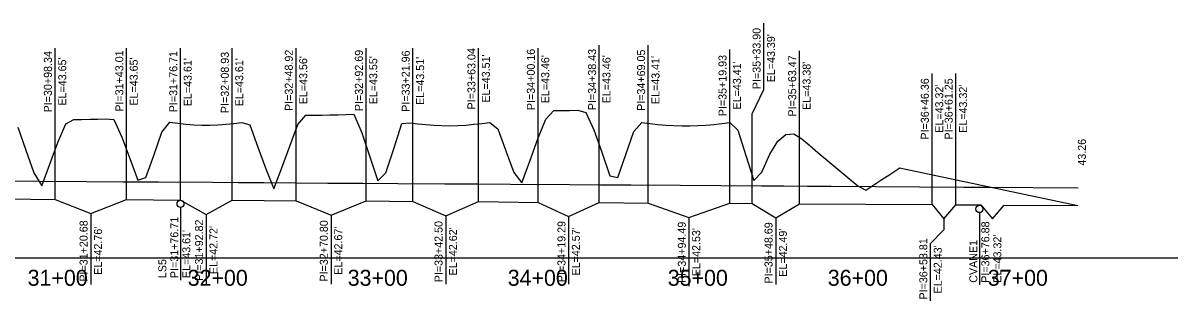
# Model space of a CAD drawing. Extents: x 2394206 to 2397081, y 556531 to 561531.
# Drawn here: x 2396359 to 2397081, y 559004 to 559178 of the extents above; entities that cross this region are included whole.
import ezdxf

# ---------------------------------------------------------------- set-up
doc = ezdxf.new("R2010")
doc.units = 0
for name, color, linetype in [('Default', 7, 'Continuous'), ('Existing ground', 7, 'Continuous'), ('Profile grid', 7, 'Continuous'), ('Proposed bankfull', 7, 'Continuous'), ('Proposed structure lables', 7, 'Continuous'), ('Station lables', 7, 'Continuous')]:
    doc.layers.add(name, color=color, linetype=linetype)

msp = doc.modelspace()

# ---------------------------------------------------------------- linework, layer by layer
at = {"layer": 'Default'}
for p, q in [((2396822.06, 559136.3), (2396822.06, 559177.88)), ((2396379.18, 559067.7), (2396379.18, 559162.16)), ((2396423.85, 559067.66), (2396423.85, 559162.16)), ((2396457.55, 559067.27), (2396457.55, 559162.16)), ((2396489.77, 559067.24), (2396489.77, 559162.16)), ((2396529.76, 559066.76), (2396529.76, 559162.16)), ((2396573.53, 559066.71), (2396573.53, 559162.16)), ((2396602.8, 559066.31), (2396602.8, 559162.16)), ((2396643.88, 559066.27), (2396643.88, 559162.16)), ((2396681, 559065.83), (2396681, 559162.16)), ((2396719.27, 559065.79), (2396719.27, 559164.02)), ((2396749.89, 559065.33), (2396749.89, 559164.02)), ((2396800.77, 559065.28), (2396800.77, 559161.41)), ((2396844.31, 559065.01), (2396844.31, 559160.5)), ((2396927.2, 559064.41), (2396927.2, 559146.32)), ((2396942.09, 559064.39), (2396942.09, 559146.32)), ((2396814.74, 559121.08), (2396822.06, 559136.3)), ((2396814.74, 559065.04), (2396814.74, 559121.08)), ((2396401.52, 559058.8), (2396401.52, 559014.54)), ((2396473.66, 559058.34), (2396473.66, 559014.74)), ((2396551.64, 559057.85), (2396551.64, 559014.74)), ((2396623.34, 559057.4), (2396623.34, 559014.74)), ((2396700.13, 559056.91), (2396700.13, 559014.74)), ((2396775.33, 559056.44), (2396775.33, 559013.52)), ((2396829.53, 559056.1), (2396829.53, 559014.52)), ((2396934.65, 559055.44), (2396934.65, 559048.76)), ((2396934.65, 559048.76), (2396925.98, 559039.81)), ((2396925.98, 559039.81), (2396925.98, 559004.24))]:
    msp.add_line(p, q, dxfattribs=at)
at = {"layer": 'Existing ground'}
for points in [[(2396355.84, 559112.93), (2396360.84, 559098.53), (2396365.84, 559084.3), (2396370.84, 559076.18), (2396375.84, 559089.71), (2396380.84, 559103.22), (2396385.84, 559114.93), (2396390.84, 559117.6), (2396395.84, 559117.64), (2396400.84, 559117.73), (2396405.84, 559117.86), (2396410.84, 559118.02), (2396415.84, 559117.55), (2396420.84, 559106.59), (2396425.84, 559093.2), (2396430.84, 559079.64), (2396435.84, 559081.35), (2396440.84, 559095.21), (2396445.84, 559109.68), (2396450.84, 559115.95), (2396455.84, 559115.34), (2396460.84, 559114.76), (2396465.84, 559114.34), (2396470.84, 559114.11), (2396475.84, 559114.08), (2396480.84, 559114.25), (2396485.84, 559114.62), (2396490.84, 559115.16), (2396495.84, 559115.76), (2396500.84, 559114.36), (2396505.84, 559100.34), (2396510.84, 559086.88), (2396515.84, 559074.27), (2396520.84, 559087.43), (2396525.84, 559100.88), (2396530.84, 559114.4), (2396535.84, 559120.3), (2396540.84, 559120.31), (2396545.84, 559120.36), (2396550.84, 559120.46), (2396555.84, 559120.6), (2396560.84, 559120.79), (2396565.84, 559121), (2396570.84, 559109.35), (2396575.84, 559094.31), (2396580.84, 559079.21), (2396585.84, 559084.22), (2396590.84, 559099.3), (2396595.84, 559115.12), (2396600.84, 559115.61), (2396605.84, 559114.95), (2396610.84, 559114.42), (2396615.84, 559114.03), (2396620.84, 559113.81), (2396625.84, 559113.76), (2396630.84, 559113.88), (2396635.84, 559114.17), (2396640.84, 559114.62), (2396645.84, 559115.19), (2396650.84, 559115.8), (2396655.84, 559111.83), (2396660.84, 559097.98), (2396665.84, 559084.5), (2396670.84, 559077.95), (2396675.84, 559091.61), (2396680.84, 559105.46), (2396685.84, 559117.8), (2396690.84, 559123.18), (2396695.84, 559123.23), (2396700.84, 559123.33), (2396705.84, 559123.48), (2396710.84, 559122.04), (2396715.84, 559111.16), (2396720.84, 559097.17), (2396725.84, 559082.46), (2396730.84, 559081.32), (2396735.84, 559095.72), (2396740.84, 559110.11), (2396745.84, 559115.8), (2396750.84, 559115.15), (2396755.84, 559114.59), (2396760.84, 559114.14), (2396765.84, 559113.83), (2396770.84, 559113.67), (2396775.84, 559113.65), (2396780.84, 559113.79)], [(2396780.84, 559113.79), (2396785.84, 559114.07), (2396790.84, 559114.49), (2396795.84, 559115.03), (2396800.84, 559115.69), (2396805.84, 559110.95), (2396810.84, 559095.19), (2396815.84, 559079.49), (2396820.84, 559084.67), (2396825.84, 559096), (2396830.84, 559103.98), (2396835.84, 559108.33), (2396840.84, 559108.76), (2396845.84, 559105.48), (2396850.84, 559101.29), (2396855.84, 559097.09), (2396860.84, 559092.9), (2396865.84, 559088.71), (2396870.84, 559084.52), (2396875.84, 559080.32), (2396880.84, 559076.13), (2396885.84, 559073.39), (2396890.84, 559076.71), (2396895.84, 559080.03), (2396900.84, 559083.35), (2396905.84, 559086.67), (2396906.94, 559087.4), (2397018.36, 559063.78)]]:
    msp.add_lwpolyline(points, dxfattribs=at)
at = {"layer": 'Profile grid'}
msp.add_line((2394280.84, 559031.18), (2397080.84, 559031.18), dxfattribs=at)
at = {"layer": 'Proposed bankfull'}
for points in [[(2396345.75, 559079.22), (2396368.74, 559079.08), (2396399.12, 559078.88), (2396421.46, 559078.74), (2396443.79, 559078.59), (2396477.49, 559078.38), (2396493.6, 559078.27), (2396509.71, 559078.17), (2396549.7, 559077.92), (2396571.58, 559077.78), (2396593.47, 559077.63), (2396622.74, 559077.45), (2396643.28, 559077.32), (2396663.82, 559077.18), (2396700.94, 559076.95), (2396720.07, 559076.82), (2396739.21, 559076.7), (2396769.83, 559076.5), (2396795.27, 559076.34), (2396820.71, 559076.18), (2396834.68, 559076.09), (2396849.47, 559075.99), (2396864.25, 559075.9), (2396947.14, 559075.37), (2396954.59, 559075.32)], [(2396954.59, 559075.32), (2396962.03, 559075.27), (2397018.43, 559074.91)]]:
    msp.add_lwpolyline(points, dxfattribs=at)
at = {"layer": 'Proposed structure lables'}
for p, q in [((2396348.8, 559068.13), (2396379.18, 559067.7)), ((2396379.18, 559067.7), (2396401.52, 559058.8)), ((2396401.52, 559058.8), (2396423.85, 559067.66)), ((2396423.85, 559067.66), (2396457.55, 559067.27)), ((2396457.55, 559067.27), (2396473.66, 559058.34)), ((2396473.66, 559058.34), (2396489.77, 559067.24)), ((2396489.77, 559067.24), (2396529.76, 559066.76)), ((2396529.76, 559066.76), (2396551.64, 559057.85)), ((2396551.64, 559057.85), (2396573.53, 559066.71)), ((2396573.53, 559066.71), (2396602.8, 559066.31)), ((2396602.8, 559066.31), (2396623.34, 559057.4)), ((2396623.34, 559057.4), (2396643.88, 559066.27)), ((2396643.88, 559066.27), (2396681, 559065.83)), ((2396681, 559065.83), (2396700.13, 559056.91)), ((2396700.13, 559056.91), (2396719.27, 559065.79)), ((2396719.27, 559065.79), (2396749.89, 559065.33)), ((2396749.89, 559065.33), (2396775.33, 559056.44)), ((2396775.33, 559056.44), (2396800.77, 559065.28)), ((2396800.77, 559065.28), (2396814.74, 559065.04)), ((2396814.74, 559065.04), (2396829.53, 559056.1)), ((2396829.53, 559056.1), (2396844.31, 559065.01)), ((2396844.31, 559065.01), (2396927.2, 559064.41)), ((2396927.2, 559064.41), (2396934.65, 559055.44)), ((2396934.65, 559055.44), (2396942.09, 559064.39)), ((2396942.09, 559064.39), (2396957.72, 559064.27)), ((2396957.72, 559064.27), (2396965.06, 559055.44)), ((2396965.06, 559055.44), (2396972.3, 559064.15)), ((2396972.3, 559064.15), (2397018.36, 559063.78)), ((2396457.57, 559062.58), (2396457.57, 559017.21)), ((2396956.88, 559059.4), (2396956.88, 559014.31))]:
    msp.add_line(p, q, dxfattribs=at)
for centre in [(2396457.57, 559064.88), (2396956.82, 559061.69)]:
    msp.add_ellipse(centre, major_axis=(0, -2.29), ratio=0.950348, dxfattribs=at)

# ---------------------------------------------------------------- texts
for s, p in [('PI=35+33.90', (2396820.06, 559136.62)), ("EL=43.39'", (2396829.06, 559140.87)), ('PI=30+98.34', (2396377.18, 559122.08)), ('PI=31+43.01', (2396421.85, 559122.51)), ('PI=31+76.71', (2396455.55, 559122.13)), ('PI=32+08.93', (2396487.77, 559121.62)), ('PI=32+48.92', (2396527.76, 559122.96)), ('PI=32+92.69', (2396571.53, 559122.87)), ('PI=33+21.96', (2396600.8, 559122.47)), ('PI=33+63.04', (2396641.88, 559123.95)), ("EL=43.51'", (2396650.88, 559128.2)), ('PI=34+00.16', (2396679, 559123.51)), ('PI=34+38.43', (2396717.27, 559123.47)), ('PI=34+69.05', (2396747.89, 559123.01)), ("EL=43.65'", (2396386.18, 559126.33)), ("EL=43.65'", (2396430.85, 559126.29)), ("EL=43.61'", (2396464.55, 559125.9)), ("EL=43.61'", (2396496.77, 559125.87)), ("EL=43.56'", (2396536.76, 559127.16)), ("EL=43.55'", (2396580.53, 559127.12)), ("EL=43.51'", (2396609.8, 559126.72)), ("EL=43.46'", (2396688, 559127.76)), ("EL=43.46'", (2396726.27, 559127.72)), ("EL=43.41'", (2396756.89, 559127.26)), ('PI=35+19.93', (2396798.77, 559119.67)), ("EL=43.41'", (2396807.77, 559123.91)), ('PI=35+63.47', (2396842.31, 559119.44)), ("EL=43.38'", (2396851.31, 559123.64)), ('PI=36+46.36', (2396925.2, 559105.1)), ("EL=43.32'", (2396934.2, 559109.35)), ('PI=36+61.25', (2396940.09, 559105.08)), ("EL=43.32'", (2396949.09, 559109.33)), ('43.26', (2397023.36, 559088.78)), ('PI=31+20.68', (2396399.52, 559016.29)), ("EL=42.76'", (2396408.52, 559020.54)), ('PI=31+76.71', (2396456.21, 559018.49)), ('PI=31+92.82', (2396471.66, 559016.79)), ("EL=42.72'", (2396480.66, 559020.99)), ('PI=32+70.80', (2396549.64, 559016.34)), ("EL=42.67'", (2396558.64, 559020.59)), ('PI=33+42.50', (2396621.34, 559015.89)), ("EL=42.62'", (2396630.34, 559020.14)), ('PI=34+19.29', (2396698.13, 559015.88)), ("EL=42.57'", (2396707.13, 559020.13)), ('PI=34+94.49', (2396773.33, 559015.43)), ('PI=35+48.69', (2396827.53, 559015.09)), ('PI=36+76.88', (2396963.01, 559015.59)), ("EL=43.61'", (2396463.71, 559018.49)), ("EL=42.53'", (2396782.33, 559019.68)), ("EL=42.49'", (2396836.53, 559019.34)), ('PI=36+53.81', (2396924.26, 559005.12)), ("EL=43.32'", (2396970.51, 559015.59)), ("EL=42.43'", (2396933.26, 559008.89)), ('CVANE1', (2396955.51, 559015.59)), ('LS5', (2396448.71, 559018.49))]:
    msp.add_text(s, height=5, rotation=90, dxfattribs=at).set_placement(p)
at = {"layer": 'Station lables'}
for s, p in [('31+00', (2396362.05, 559013.68)), ('32+00', (2396462.05, 559013.68)), ('33+00', (2396562.05, 559013.68)), ('34+00', (2396662.05, 559013.68)), ('35+00', (2396762.05, 559013.68)), ('36+00', (2396862.05, 559013.68)), ('37+00', (2396962.05, 559013.68))]:
    msp.add_text(s, height=10, dxfattribs=at).set_placement(p)

doc.saveas('drawing.dxf')
